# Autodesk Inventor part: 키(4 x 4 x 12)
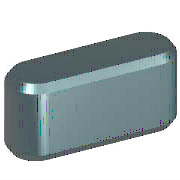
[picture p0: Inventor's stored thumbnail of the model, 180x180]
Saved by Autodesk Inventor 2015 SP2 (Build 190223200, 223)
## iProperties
IsCustomPart: 0
Created: 2009-02
Part Number: 키(4 x 4 x 12)
Material: 강철, 연강
Description: 키 및 해당 키홈
Document SubType Name: Modeling
Standard: KS B 1311
Designer: KYOUNG IL JANG
Standards Organization: KS
Language: ko-KR
Size Designation: 4 x 4 x 12
Categories: <MemberInstance><Categories><Category DisplayName="샤프트 부품" InternalName="7f7aeb1f-a693-4053-b835-cee3144e0d98" Mnemonic="SHFT"><Category DisplayName="키" Interna
Density: 7.86 g/cm^3
Mass: 1.38739 g
Surface Area: 1.94869 cm^2
Volume: 0.176513 cm^3
Appearance: 강철
Author: KYOUNG IL JANG
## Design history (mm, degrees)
workplane "Work Plane1"
workplane "Work Plane2"
sketch "스케치1"
  geometry: L1 (2, 2)-(10, 2); L2 (10, -2)-(2, -2); L3 (0, 9.4)-(0, -7.4) reference; L4 (-5, 0)-(30, 0) reference; L5 (12, 0)-(12, 7); A1 r 2 centre (2, 0) between (2, 2) and (2, -2); A2 r 2 centre (10, 0) between (10, -2) and (10, 2)
  constraints: 6 end point, 5 point on circle, 4 tangent, 3 point on line, 2 centre point, 1 horizontal, 1 parallel, 1 perpendicular
  dimensions: "d0" = 2 radius of A1 (= 0.5 x PB); "d13" = 2 radius of A2 (= 0.5 x PB); "d14" = 12 distance between parallel lines of L5 L3 (= NLG)
extrude "본체1" new body sketch "스케치1" taper "d3" = 0 deg; stored distance "d4" = 10
workplane "Work Plane3"
body "Solid1"
chamfer "모따기1" distance "d8" = 0.25 (= PHH); stored, may be unused: second distance "d9" = 0.25 (= PHH), angle "d15" = 45 deg
other parameters: "d1" = -2.5 (= -PNT), "d2" = 1.5 (= PH - PNT), "NLG" = 12 [user parameter; used in 3 equation terms], "PB" = 4 [user parameter; used in 2 equation terms], "PNT" = 2.5 [user parameter; used in 2 equation terms], "PH" = 4 [user parameter; used in 1 equation term], "PHH" = 0.25 [user parameter; used in 2 equation terms], "d10" = 0, "d16" = 0, "d17" = 0, "d18" = 0, "PLB2" = 12 (= NLG) [user parameter], "WDMAX" = 12 [user parameter], "PLB1" = 12 (= NLG) [user parameter], "RR" = 0.08 [user parameter], "PUEB" = 1.8 [user parameter]
